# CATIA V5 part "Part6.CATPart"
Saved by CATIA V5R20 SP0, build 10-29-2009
Part number: Part6
Bounding box of the stored display mesh (mm): x 0 to 0, y -19.671 to 48.284, z 73.126 to 73.663
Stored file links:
  C:\Documents and Settings\Media\Escritorio\GATO_ALAMBRICO\Part6.CATPart
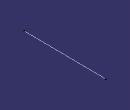
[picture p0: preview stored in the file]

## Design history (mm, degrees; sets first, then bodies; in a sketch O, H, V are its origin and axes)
Set1
  Line1: type PtPt, FirstPoint Point1, SecondPoint Point2, Start 20, End 20
  Point1: stored without definition
  Point2: stored without definition
Body1 (main body)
